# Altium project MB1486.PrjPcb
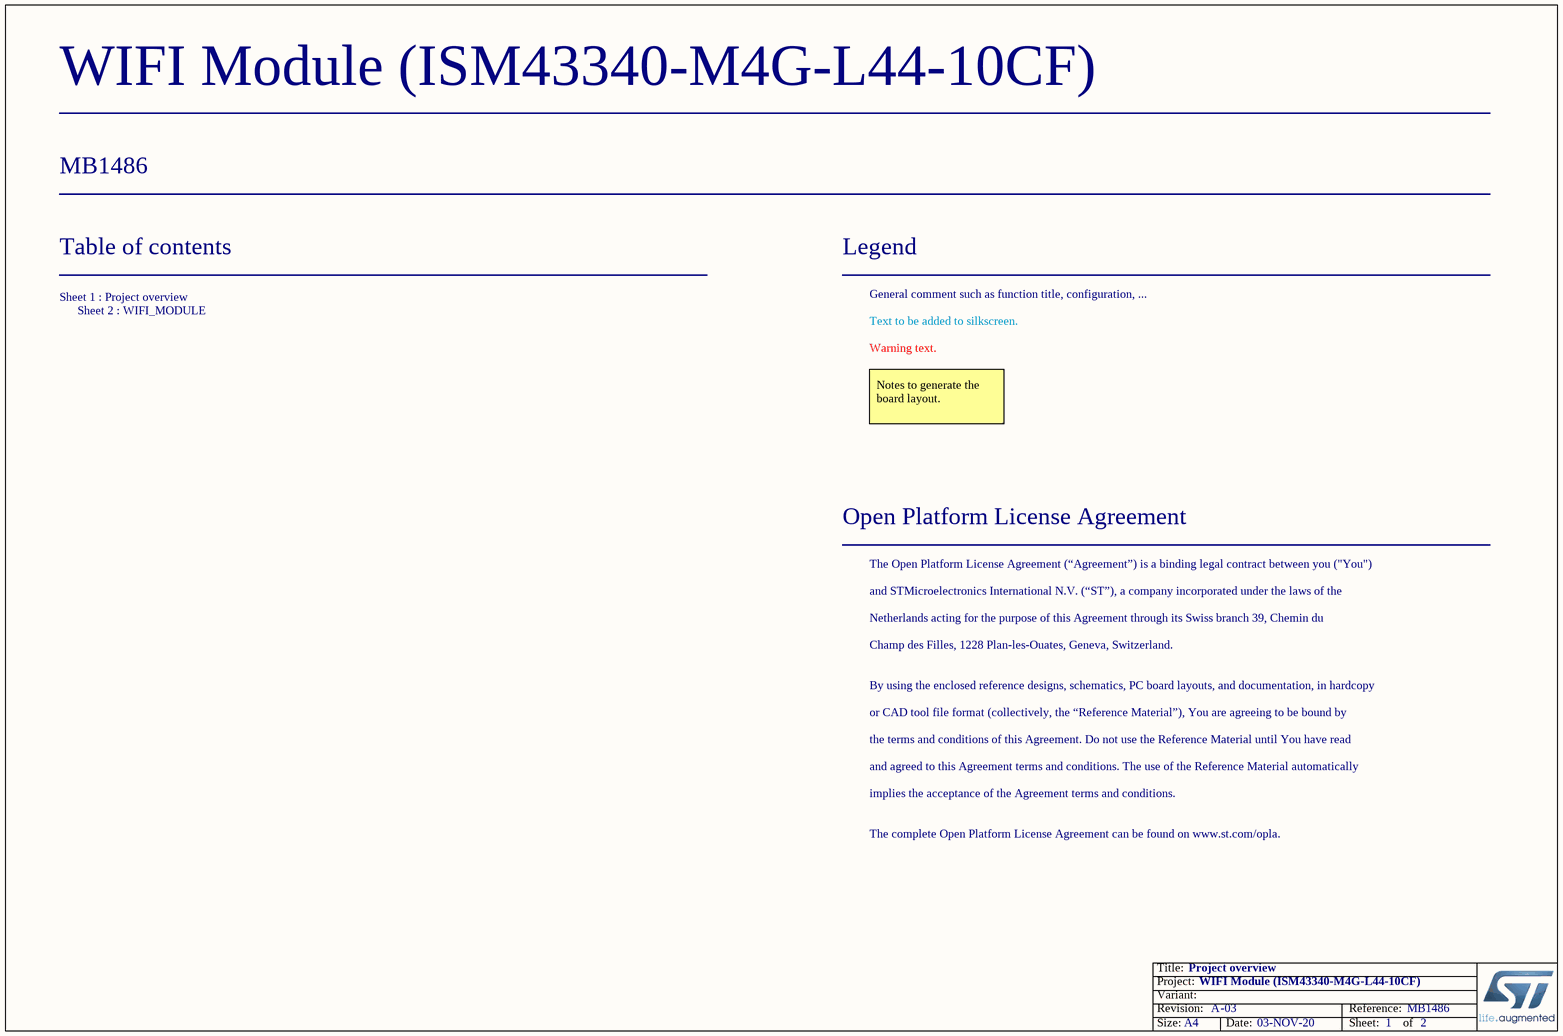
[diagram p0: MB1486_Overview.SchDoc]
Board_Reference: MB1486; Board_PCB_Revision: A; Board_Name: WIFI Module (ISM43340-M4G-L44-10CF); Board_Document_Date: 03-NOV-20; Board_Assembly_Revision: 03
2 sheets, 27 parts. Net scope: global (net labels, ports and power ports of the same name join across sheets).
Board file: MB1486.PcbDoc
Sheets:
  MB1486_Overview.SchDoc
  WIFI_MODULE.SchDoc

## Sheet MB1486_Overview.SchDoc: Project overview
size A4; Date: Not used; ApprovedBy: Not used; CheckedBy: Not used; Author: Not used; CompanyName: STMicroelectronics; DrawnBy: Not used; Engineer: Not used; Organization: Not used; Address1: Not used; Address2: Not used; Address3: Not used; Address4: Not used; DocumentNumber: Not used; Revision: Not used; SheetNumber: 1; SheetTotal: 2

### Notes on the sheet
- Table of contents
- Legend
- General comment such as function title, configuration, ...
- Text to be added to silkscreen.
- Warning text.
- Notes to generate the board layout.
- Sheet 1 : Project overview
  Sheet 2 : WIFI_MODULE
- Open Platform License Agreement
- The Open Platform License Agreement (“Agreement”) is a binding legal contract between you ("You")
- and STMicroelectronics International N.V. (“ST”), a company incorporated under the laws of the
- Netherlands acting for the purpose of this Agreement through its Swiss branch 39, Chemin du
- Champ des Filles, 1228 Plan-les-Ouates, Geneva, Switzerland.
- By using the enclosed reference designs, schematics, PC board layouts, and documentation, in hardcopy
- or CAD tool file format (collectively, the “Reference Material”), You are agreeing to be bound by
- the terms and conditions of this Agreement. Do not use the Reference Material until You have read
- and agreed to this Agreement terms and conditions. The use of the Reference Material automatically
- implies the acceptance of the Agreement terms and conditions.
- The complete Open Platform License Agreement can be found on www.st.com/opla.

## Sheet WIFI_MODULE.SchDoc: WIFI-BT_MODULE
size A3; Date: Not used; ApprovedBy: Not used; CheckedBy: Not used; Author: Not used; CompanyName: STMicroelectronics; DrawnBy: Not used; Engineer: Not used; Organization: Not used; Address1: Not used; Address2: Not used; Address3: Not used; Address4: Not used; DocumentNumber: Not used; Revision: Not used; SheetNumber: 2; SheetTotal: 2
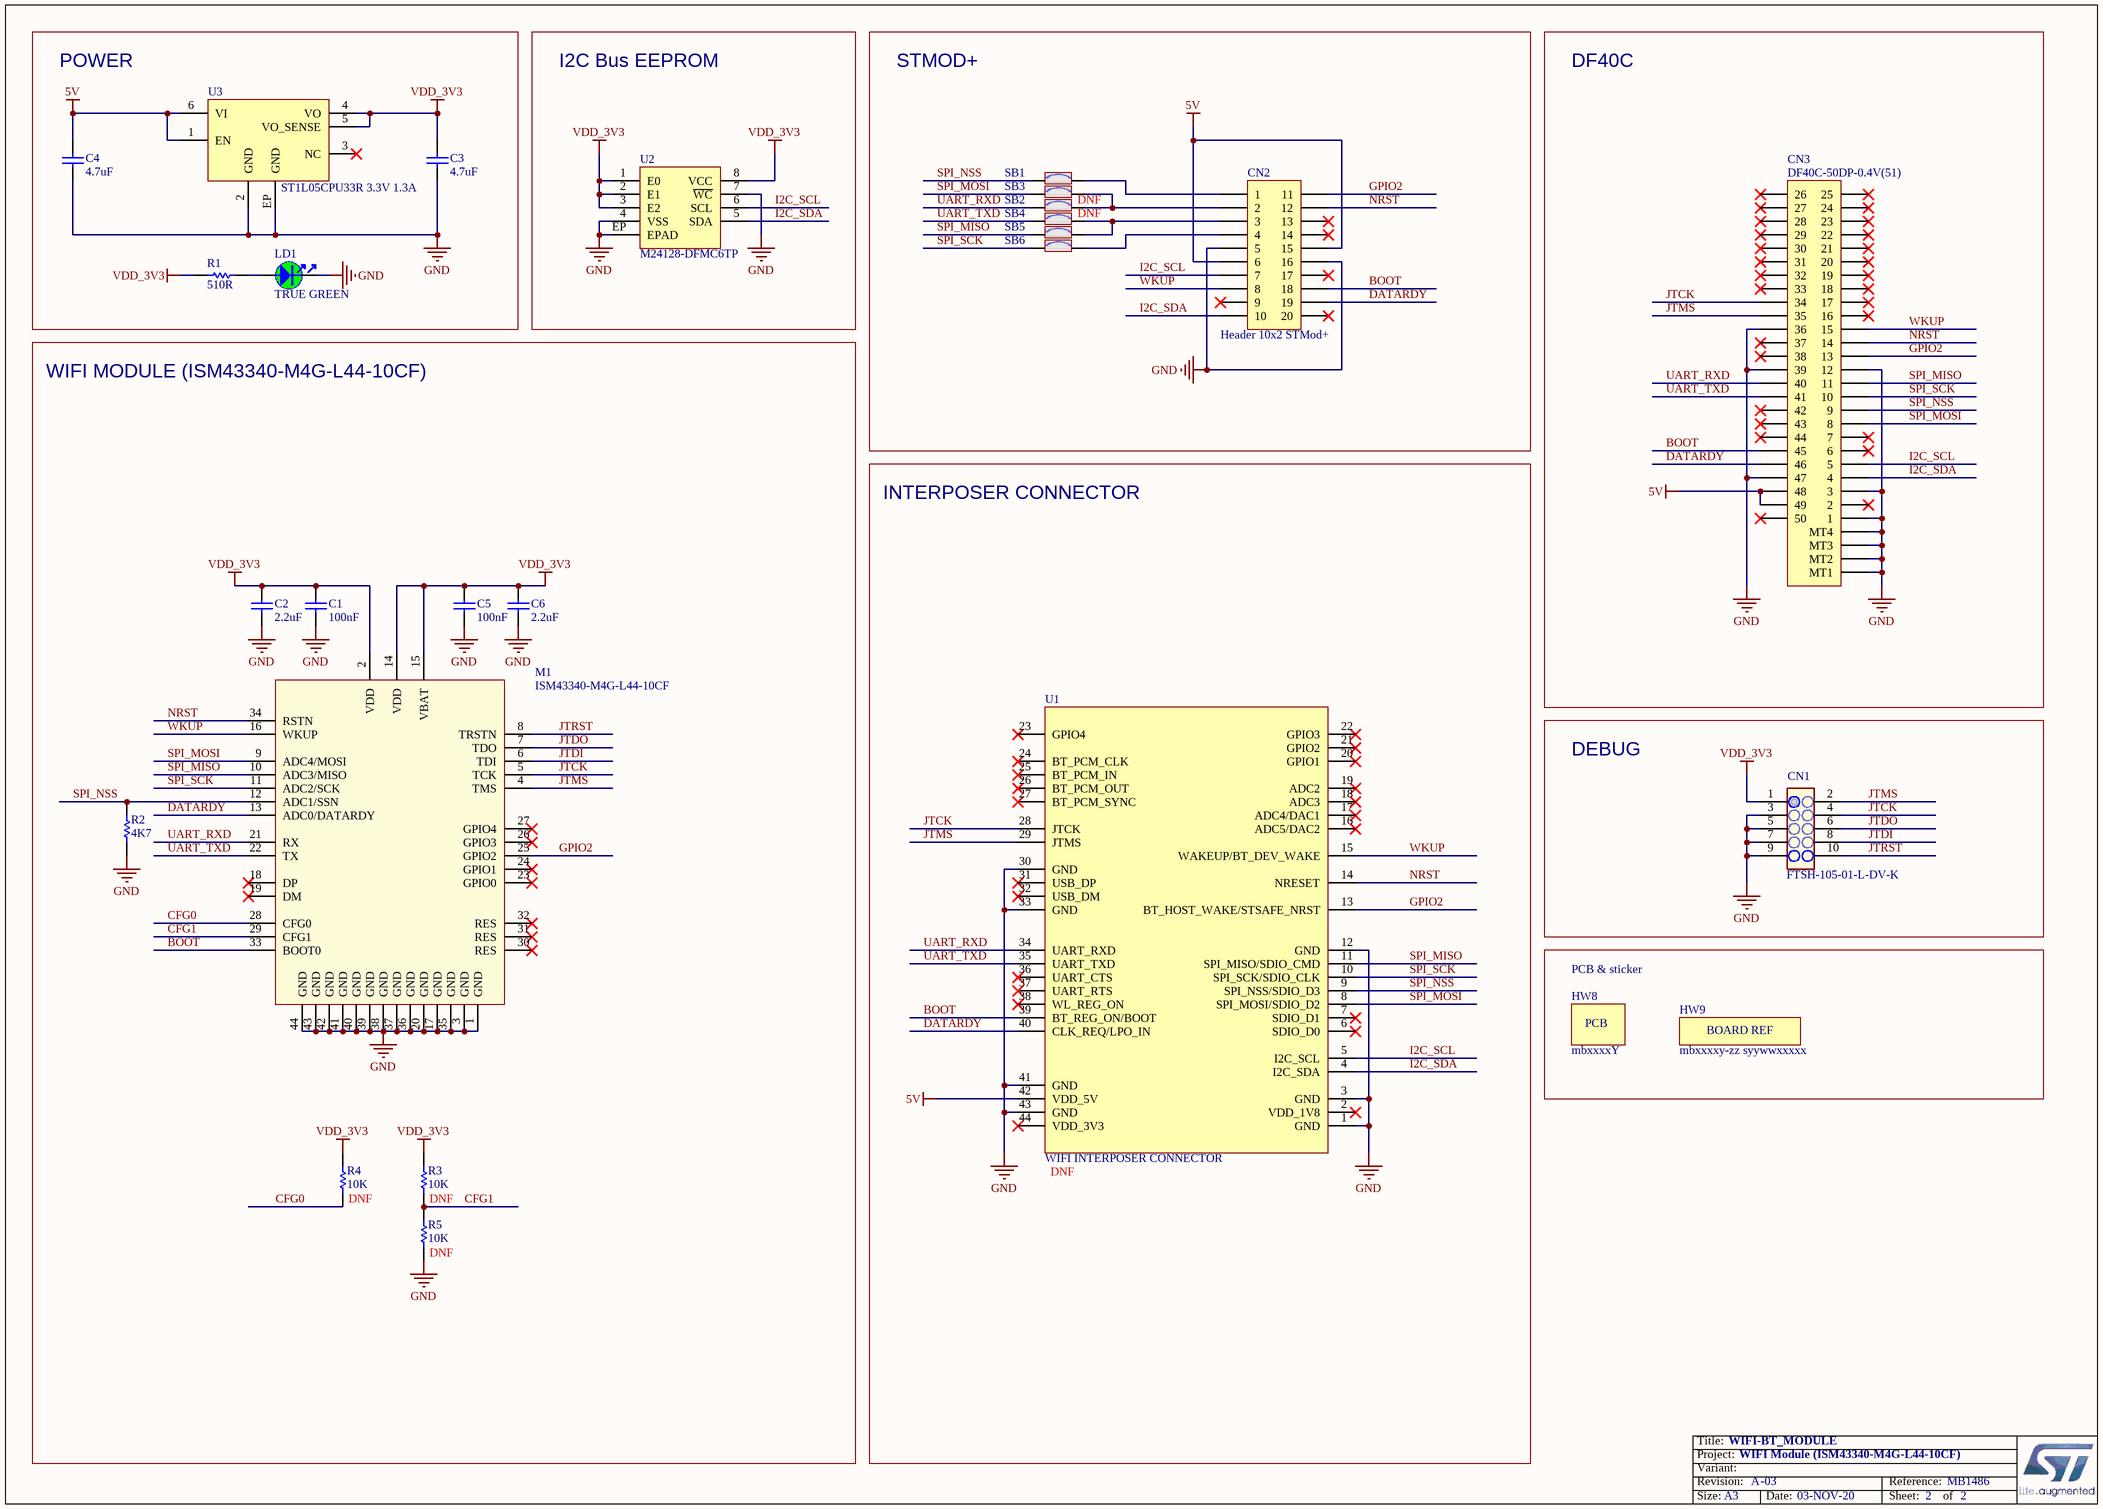
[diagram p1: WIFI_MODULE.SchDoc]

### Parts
C1  value 100nF  [C0402]  (hidden comment: Capacitor)
C2  value 2.2uF  [C0603]  (hidden comment: Capacitor)
C3  value 4.7uF  [C0603]  (hidden comment: Capacitor)
C4  value 4.7uF  [C0603]  (hidden comment: Capacitor)
C5  value 100nF  [C0402]  (hidden comment: Capacitor)
C6  value 2.2uF  [C0603]  (hidden comment: Capacitor)
CN1  value FTSH-105-01-L-DV-K  [CON_SAMTEC_FTSH-105-01-L-DV-K]  (hidden comment: Header 5x2 Generic)
CN2  Header 10x2 STMod+  [CON_SAMTEC_TMM-110-01-L-D-RA__STMOD+]
CN3  DF40C-50DP-0.4V(51)  [CON_HRS_DF40C-50DP-0.4V_51]
HW8  value mbxxxxY  (hidden comment: PCB)  (no BOM)
HW9  value mbxxxxy-zz syywwxxxxx  [STICKER_BOARD-REF_25X5]  (hidden comment: STICKER_BOARD_REF)  (no BOM)
LD1  value TRUE GREEN  [LED_0603_VISHAY_VLMTG1300-GS08_GREEN_1A2K_H0P8]  (hidden comment: LED_green)
M1  value ISM43340-M4G-L44-10CF  [MOD_WIFI_INVENTEK-SYSTEMS_ISM43362-M3G-L44-E-SPI-CXX]  (hidden comment: ISM43362-M3G-L44-E)
R1  value 510R  [R0402]  (hidden comment: Resistor)
R2  value 4K7  [R0402]  (hidden comment: Resistor)
R3  value 10K  [R0402]  (hidden comment: Resistor)
R4  value 10K  [R0402]  (hidden comment: Resistor)
R5  value 10K  [R0402]  (hidden comment: Resistor)
SB1  SB_ON  [SOLDER-BRIDGE_R0603-0R]  (value not drawn)
SB2  SB_ON  [SOLDER-BRIDGE_R0603-0R]  (value not drawn)
SB3  SB_ON  [SOLDER-BRIDGE_R0603-0R]  (value not drawn)
SB4  SB_ON  [SOLDER-BRIDGE_R0603-0R]  (value not drawn)
SB5  SB_ON  [SOLDER-BRIDGE_R0603-0R]  (value not drawn)
SB6  SB_ON  [SOLDER-BRIDGE_R0603-0R]  (value not drawn)
U1  value WIFI INTERPOSER CONNECTOR  [CON_MOD2BOARD_WIFI_MURATA_LBEE5PA1LD]  (hidden comment: WIFI MODULE INTERPOSER)  (no BOM)
U2  M24128-DFMC6TP  [ICC_DFN8-EPAD_2X3_P050]
U3  value ST1L05CPU33R 3.3V 1.3A  [ICC_DFN6-EPAD_3X3_P095]  (hidden comment: ST1L05CPU33R)

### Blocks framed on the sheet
POWER: C3 C4 LD1 R1 U3
I2C Bus EEPROM: U2
STMOD+: CN2 SB1-SB6
DF40C: CN3
WIFI MODULE (ISM43340-M4G-L44-10CF): C1 C2 C5 C6 M1 R2-R5
INTERPOSER CONNECTOR: U1
DEBUG: CN1
PCB & sticker: HW8 HW9

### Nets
5V: C4.2 CN2.6 CN2.15 CN3.48 CN3.49 U1.42(VDD_5V) U3.1(EN) U3.6(VI)
GND: C1.1 C2.1 C3.1 C4.1 C5.1 C6.1 CN1.3 CN1.5 CN1.7 CN1.9 CN2.5 CN2.16 CN3.1 CN3.3 CN3.12 CN3.36 CN3.39 CN3.47 CN3.MT1 CN3.MT2 CN3.MT3 CN3.MT4 LD1.2 M1.1(GND) M1.3(GND) M1.17(GND) M1.20(GND) M1.35(GND) M1.36(GND) M1.37(GND) M1.38(GND) M1.39(GND) M1.40(GND) M1.41(GND) M1.42(GND) M1.43(GND) M1.44(GND) R2.1 R5.1 U1.1(GND) U1.3(GND) U1.12(GND) U1.30(GND) U1.33(GND) U1.41(GND) U1.43(GND) U2.4(VSS) U2.7(~{WC}) U2.EP(EPAD) U3.2(GND) U3.EP(GND)
VDD_3V3: C1.2 C2.2 C3.2 C5.2 C6.2 CN1.1 M1.2(VDD) M1.14(VDD) M1.15(VBAT) R1.1 R3.2 R4.2 U2.1(E0) U2.2(E1) U2.3(E2) U2.8(VCC) U3.4(VO) U3.5(VO_SENSE)
BOOT: CN2.18 CN3.45 M1.33(BOOT0) U1.39(BT_REG_ON/BOOT)
CFG0: M1.28(CFG0) R4.1
CFG1: M1.29(CFG1) R3.1 R5.2
DATARDY: CN2.19 CN3.46 M1.13(ADC0/DATARDY) U1.40(CLK_REQ/LPO_IN)
GPIO2: CN2.11 CN3.13 M1.25(GPIO2) U1.13(BT_HOST_WAKE/STSAFE_NRST)
I2C_SCL: CN2.7 CN3.5 U1.5(I2C_SCL) U2.6(SCL)
I2C_SDA: CN2.10 CN3.4 U1.4(I2C_SDA) U2.5(SDA)
JTCK: CN1.4 CN3.34 M1.5(TCK) U1.28(JTCK)
JTDI: CN1.8 M1.6(TDI)
JTDO: CN1.6 M1.7(TDO)
JTMS: CN1.2 CN3.35 M1.4(TMS) U1.29(JTMS)
JTRST: CN1.10 M1.8(TRSTN)
NRST: CN2.12 CN3.14 M1.34(RSTN) U1.14(NRESET)
SPI_MISO: CN3.11 M1.10(ADC3/MISO) SB5.1 U1.11(SPI_MISO/SDIO_CMD)
SPI_MOSI: CN3.8 M1.9(ADC4/MOSI) SB3.1 U1.8(SPI_MOSI/SDIO_D2)
SPI_NSS: CN3.9 M1.12(ADC1/SSN) R2.2 SB1.1 U1.9(SPI_NSS/SDIO_D3)
SPI_SCK: CN3.10 M1.11(ADC2/SCK) SB6.1 U1.10(SPI_SCK/SDIO_CLK)
UART_RXD: CN3.40 M1.21(RX) SB2.1 U1.34(UART_RXD)
UART_TXD: CN3.41 M1.22(TX) SB4.1 U1.35(UART_TXD)
WKUP: CN2.8 CN3.15 M1.16(WKUP) U1.15(WAKEUP/BT_DEV_WAKE)
NetCN2_1: CN2.1 SB1.2
NetCN2_2: CN2.2 SB2.2 SB3.2
NetCN2_3: CN2.3 SB4.2 SB5.2
NetCN2_4: CN2.4 SB6.2
NetLD1_1: LD1.1 R1.2

Not connected (* = marked no-connect by the designer): CN2 9* 13* 14* 17* 20*; CN3 2* 6* 7* 16* 17* 18* 19* 20* 21* 22* 23* 24* 25* 26* 27* 28* 29* 30* 31* 32* 33* 37* 38* 42* 43* 44* 50*; M1 18(DP)* 19(DM)* 23(GPIO0)* 24(GPIO1)* 26(GPIO3)* 27(GPIO4)* 30(RES)* 31(RES)* 32(RES)*; U1 2(VDD_1V8)* 6(SDIO_D0)* 7(SDIO_D1)* 16(ADC5/DAC2)* 17(ADC4/DAC1)* 18(ADC3)* 19(ADC2)* 20(GPIO1)* 21(GPIO2)* 22(GPIO3)* 23(GPIO4)* 24(BT_PCM_CLK)* 25(BT_PCM_IN)* 26(BT_PCM_OUT)* 27(BT_PCM_SYNC)* 31(USB_DP)* 32(USB_DM)* 36(UART_CTS)* 37(UART_RTS)* 38(WL_REG_ON)* 44(VDD_3V3)*; U3 3(NC)*

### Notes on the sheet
- DNF
- (near U1) DNF
- (near R4) DNF
- (near R3) DNF
- (near R5) DNF

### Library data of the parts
C1 C5 = MCD-00006: Capacitor, MLCC, 100nF, 16V, X7R, +/-10%, 0402, T=0.5mm; Part_Preference: Recommended; Manufacturer: YAGEO; Manufacturer_Part_Number: CC0402KRX7R7BB104; Alternate_Manufacturer: MURATA; Alternate_Manufacturer_Part_Number: GCM155R71C104KA55D; Order_Code_RS: 616-9701
C2 C6 = MCD-00012: Capacitor, MLCC, 2.2uF, 10V, X5R, 10%, 0603, T=0,8mm; Manufacturer_Part_Number: CC0603KRX5R6BB225; Manufacturer: YAGEO; Alternate_Manufacturer_Part_Number: C0603C225K8PACTU; Alternate_Manufacturer: KEMET; Provided_By: SUBCO; Initial_Board_Reference: MB1274
C3 C4 = MCD-00009: Capacitor, MLCC, 4.7uF, 16V, X5R, 10%, 0603, T=0.8mm; Manufacturer_Part_Number: CC0603KRX5R7BB475; Manufacturer: YAGEO; Provided_By: subcon; Initial_Board_Reference: MB1274
CN1 = MCD-00610: Surface mount, vertical male connector. Double row of 5 pins, 1.27mm pitch, 3.05mm lead. Mates with FFSD connector; Manufacturer: SAMTEC; Provided_By: Subcon; Initial_Board_Reference: MB1331
CN2 = MCD-00288: Header 10x2, 2mm, RA, TH, Height 3.20mm/3.50mm; Part_Type: Connector; Manufacturer_Part_Number: TMM-110-01-L-D-RA; Manufacturer: SAMTEC; Provided_By: SubCon; Initial_Board_Reference: MB1329
CN3 = MCD-01227: Header 25x2, 0.4mm pitch, VR, SMT, Height 1.5mm; Part_Type: Connector; Manufacturer: HIROSE; Provided_By: Subcon; Initial_Board_Reference: MB1402; Remark: put schematics symbol name.
HW8 = MCD-00216: PCB, xxxx for PCB ref, Y for revision; Part_Type: Mechanical; Provided_By: Subcon; Initial_Board_Reference: MB1319
HW9 = MCD-00235: Sticker to mention board reference + serial number; Part_Type: Mechanical; Manufacturer_Part_Number: NA; Provided_By: Subcon; Initial_Board_Reference: MB1319
LD1 = MCD-00589: LED Green, 0603 SMD, Fw Voltage = 2.8V - 3.6V; Part_Type: Display; Manufacturer_Part_Number: VLMTG1300-GS08; Manufacturer: VISHAY; Alternate_Manufacturer_Part_Number: LG Q396-PS-35; Alternate_Manufacturer: OSRAM OPTO SEMICONDUCTORS; Order_Code_RS: 7730452; Provided_By: Subcon; Initial_Board_Reference: MB1331
M1 = MCD-01991: Embedded Serial-to-WiFi Module. 802.11 a/b/g/n + Bluetooth 4.0 + MCU + Certified Antenna; Part_Type: Misc; Manufacturer: INVENTEK; ECCN_US: 5A992C; Provided_By: SUBCO
R1 = MCD-00064: Resistor,510R,0402,1%,1/16W; Manufacturer_Part_Number: RC0402FR-07510RL; Manufacturer: YAGEO; Provided_By: Subcon; Initial_Board_Reference: MB1274
R2 = MCD-00065: Resistor,4K7,0402,1%,1/16W; Manufacturer_Part_Number: RC0402FR-074K7L; Manufacturer: YAGEO; Alternate_Manufacturer_Part_Number: RT0402FRE074K7L; Provided_By: SUBCO; Initial_Board_Reference: MB1274
R3-R5 = MCD-00053: Resistor,10K,0402,1%,1/16W; Manufacturer_Part_Number: RC0402FR-0710KL; Manufacturer: YAGEO; Provided_By: SUBCO; Initial_Board_Reference: MB1274
SB1-SB6 = MCD-00071: Solder Bridge ON; Part_Type: Mechanical; Provided_By: Subcon; Initial_Board_Reference: MB1274
U1 = MCD-01334: 44 pins Generic Interposer Connector (Not Fitted : Footprint only); Provided_By: Subcon; Initial_Board_Reference: MB1332
U2 = MCD-01213: I2C Memory 3V3, 128-Kbit, 2x3x0.55mm, UFDFPN8; Part_Type: IC; Manufacturer: STMICROELECTRONICS; Provided_By: Subcon; Initial_Board_Reference: MB1402; Remark: Check symbol with EPAD number
U3 = MCD-01025: LDO, 3.3V, 1.3A, Very low quiescent current BiCMOS voltage regulator; Part_Type: IC; Manufacturer: STMICROELECTRONICS; ECCN_US: EAR99; ECCN_EU: NEC; Provided_By: STM; Initial_Board_Reference: MB1331

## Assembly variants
Soldered: not fitted CN1 CN2 CN3 R3 R4 R5 SB1 SB2 SB3 SB4 SB5 SB6 U1 U2
STMod+: not fitted CN3 R3 R4 R5 SB2 SB4 U1
DFC40: not fitted CN1 CN2 R3 R4 R5 SB1 SB2 SB3 SB4 SB5 SB6 U1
